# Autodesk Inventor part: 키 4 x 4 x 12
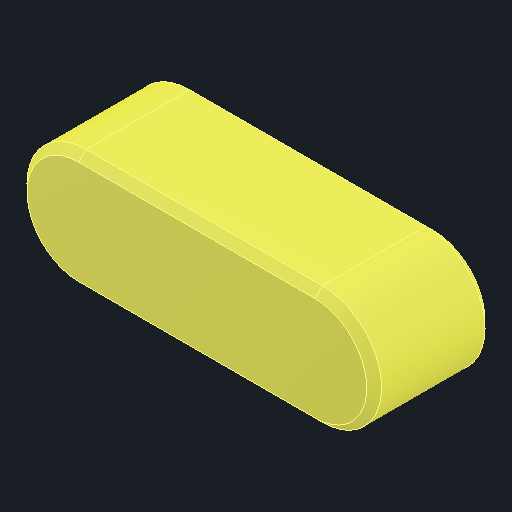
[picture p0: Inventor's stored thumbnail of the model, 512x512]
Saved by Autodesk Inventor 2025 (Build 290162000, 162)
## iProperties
Created: 2025-08
Part Number: 키 4 x 4 x 12
Material: 강철, 연강
Description: 키 및 해당 키홈
Document SubType Name: Modeling
Designer: infra11
Density: 7.85 g/cm^3
Appearance: 기본값
Author: jhkim
Sending System: Autodesk Inventor 2026
Preprocessor: ST-DEVELOPER v20.1
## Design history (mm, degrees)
feature "Solid1"
node "솔리드1"
